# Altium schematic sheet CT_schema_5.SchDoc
size 176 x 147 mm
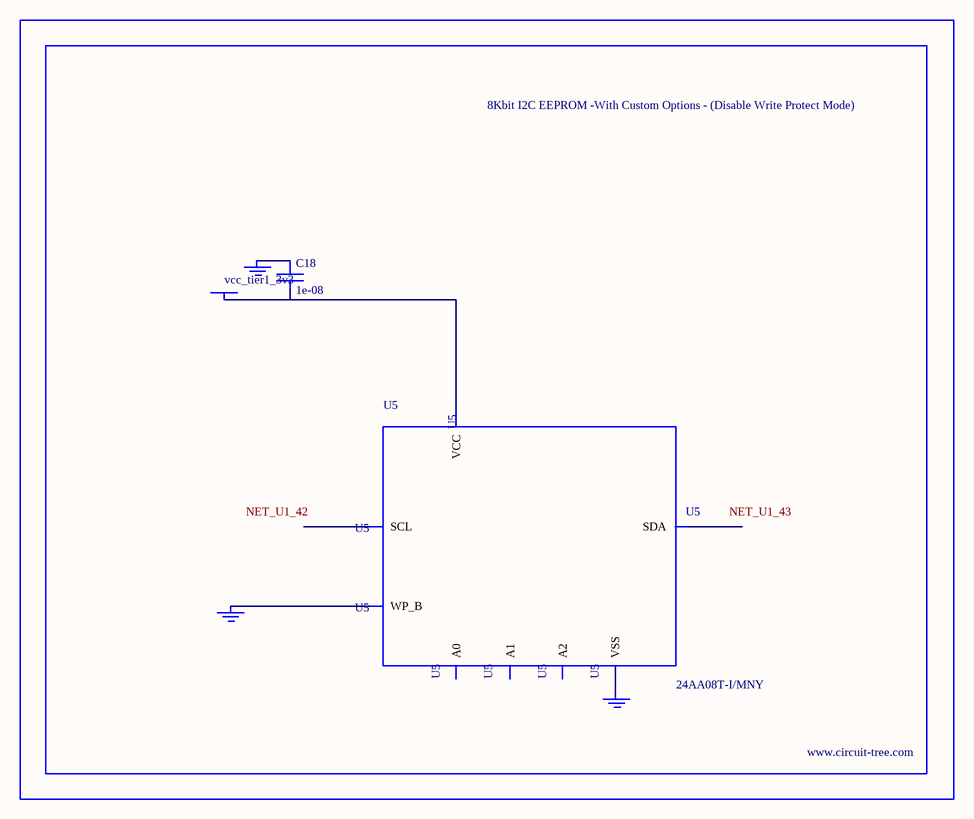
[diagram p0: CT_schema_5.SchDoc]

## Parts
BORDER4  (no value)
C18  1e-08  [C0402]
GND_INSTANCE_4_0  (no value)
GND_INSTANCE_4_1  (no value)
GND_INSTANCE_4_2  (no value)
POWER_INSTANCE_4_0  vcc_tier1_3v3
U5  24AA08T-I/MNY  [TDFN-8/6MM]

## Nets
NetC18_1: C18.1 GND_INSTANCE_4_1.0(GND)
NetC18_2: C18.2 POWER_INSTANCE_4_0.0(PWR) U5.8(VCC)
NetGND_INSTANCE_4_0_0: GND_INSTANCE_4_0.0(GND) U5.7(WP_B)
NetGND_INSTANCE_4_2_0: GND_INSTANCE_4_2.0(GND) U5.4(VSS)

Not connected (* = marked no-connect by the designer): U5 1(A0) 2(A1) 3(A2) 5(SDA) 6(SCL)

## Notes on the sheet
- Labels drawn without touching a wire or pin: NET_U1_42, NET_U1_43

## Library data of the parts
BORDER4 = BORDER_PAGE4
C18 = C0402C103K3RAC
GND_INSTANCE_4_0-GND_INSTANCE_4_2 = GND
POWER_INSTANCE_4_0 = PWR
